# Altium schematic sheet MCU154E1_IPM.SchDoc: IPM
size Letter; Date: Not shown in title block; ApprovedBy: Not shown in title block; CheckedBy: Not shown in title block; Author: Not shown in title block; CompanyName: Not shown in title block; DrawnBy: Hely Zhang; Engineer: Not shown in title block; Organization: Not shown in title block; Address1: Not shown in title block; Address2: Not shown in title block; Address3: Not shown in title block; Address4: Not shown in title block; DocumentNumber: 1; Revision: Use project parameter SCH_Rev; SheetNumber: 3; SheetTotal: 5; PageSetup: Record=PageOptions¦CenterHorizontal=True¦CenterVertical=True¦PrintScale=0.97¦XCorrection=1.00¦YCorrection=1.00¦PrintKind=0¦BorderSize=5000000¦LeftOffset=0¦BottomOffset=0¦Orientation=2¦PaperLength=1000¦PaperWidth=1000¦Scale=100¦PaperSource=15¦PrintQuality=600¦MediaType=1¦DitherType=10¦PaperKind=Letter¦PrintScaleMode=1
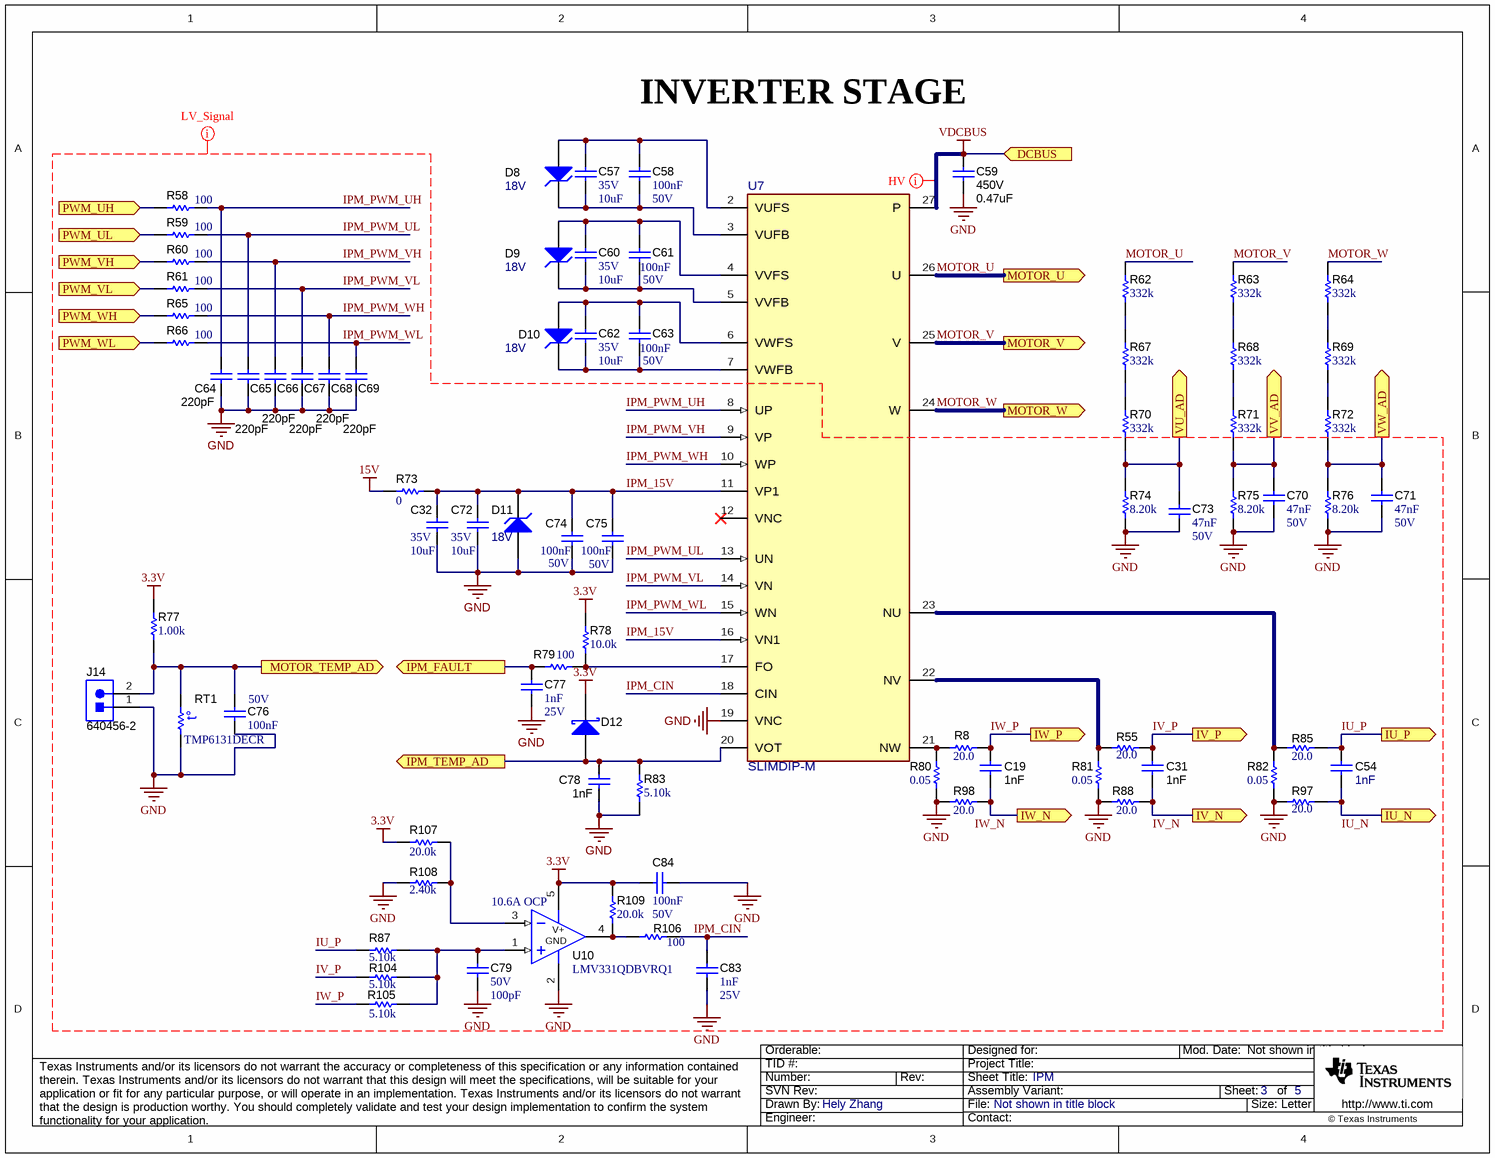
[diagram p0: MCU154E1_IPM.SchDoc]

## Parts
C19  Cap_F: 1nF  [0603]  (hidden comment: GRM188R71E102KA01D)
C31  Cap_F: 1nF  [0603]  (hidden comment: GRM188R71E102KA01D)
C32  VDC_V: 35V  ValueDisplayed: 10uF  [0805_HV]  (hidden comment: GRM21BR6YA106KE43L)
C54  Cap_F: 1nF  [0603]  (hidden comment: GRM188R71E102KA01D)
C57  VDC_V: 35V  ValueDisplayed: 10uF  [0805_HV]  (hidden comment: GRM21BR6YA106KE43L)
C58  Cap_F: 100nF  VDC_V: 50V  [0603]  (hidden comment: GCM188R71H104KA57D)
C59  VDC_V: 450V  ValueDisplayed: 0.47uF  [ECWFD_1260x650x1270]  (hidden comment: ECW-FD2W474Q1)
C60  VDC_V: 35V  ValueDisplayed: 10uF  [0805_HV]  (hidden comment: GRM21BR6YA106KE43L)
C61  Cap_F: 100nF  VDC_V: 50V  [0603]  (hidden comment: GCM188R71H104KA57D)
C62  VDC_V: 35V  ValueDisplayed: 10uF  [0805_HV]  (hidden comment: GRM21BR6YA106KE43L)
C63  Cap_F: 100nF  VDC_V: 50V  [0603]  (hidden comment: GCM188R71H104KA57D)
C64  Cap_F: 220pF  [0603]  (hidden comment: GRM188R71H221KA01D)
C65  Cap_F: 220pF  [0603]  (hidden comment: GRM188R71H221KA01D)
C66  Cap_F: 220pF  [0603]  (hidden comment: GRM188R71H221KA01D)
C67  Cap_F: 220pF  [0603]  (hidden comment: GRM188R71H221KA01D)
C68  Cap_F: 220pF  [0603]  (hidden comment: GRM188R71H221KA01D)
C69  Cap_F: 220pF  [0603]  (hidden comment: GRM188R71H221KA01D)
C70  Cap_F: 47nF  VDC_V: 50V  [0603]  (hidden comment: GRM188R71H473KA61D)
C71  Cap_F: 47nF  VDC_V: 50V  [0603]  (hidden comment: GRM188R71H473KA61D)
C72  VDC_V: 35V  ValueDisplayed: 10uF  [0805_HV]  (hidden comment: GRM21BR6YA106KE43L)
C73  Cap_F: 47nF  VDC_V: 50V  [0603]  (hidden comment: GRM188R71H473KA61D)
C74  Cap_F: 100nF  VDC_V: 50V  [0603]  (hidden comment: GCM188R71H104KA57D)
C75  Cap_F: 100nF  VDC_V: 50V  [0603]  (hidden comment: GCM188R71H104KA57D)
C76  Cap_F: 100nF  VDC_V: 50V  [0603]  (hidden comment: GCM188R71H104KA57D)
C77  Cap_F: 1nF  VDC_V: 25V  [0603]  (hidden comment: GRM188R71E102KA01D)
C78  Cap_F: 1nF  [0603]  (hidden comment: GRM188R71E102KA01D)
C79  VDC_V: 50V  ValueDisplayed: 100pF  [0603]  (hidden comment: GRM1885C1H101JA01D)
C83  Cap_F: 1nF  VDC_V: 25V  [0603]  (hidden comment: GRM188R71E102KA01D)
C84  Cap_F: 100nF  VDC_V: 50V  [0603]  (hidden comment: GCM188R71H104KA57D)
D8  value 18V  [SOD-323]  (hidden comment: MMSZ5248BS-7-F)
D9  value 18V  [SOD-323]  (hidden comment: MMSZ5248BS-7-F)
D10  value 18V  [SOD-323]  (hidden comment: MMSZ5248BS-7-F)
D11  value 18V  [SOD-323]  (hidden comment: MMSZ5248BS-7-F)
D12  BAT54T1G  [SOD-123]  (value not drawn)
J14  640456-2  [TE_640456-2]
R8  ValueDisplayed: 20.0  [0603]  (hidden comment: RC0603FR-0720RL)
R55  ValueDisplayed: 20.0  [0603]  (hidden comment: RC0603FR-0720RL)
R58  ValueDisplayed: 100  [0603]  (hidden comment: RC0603FR-07100RL)
R59  ValueDisplayed: 100  [0603]  (hidden comment: RC0603FR-07100RL)
R60  ValueDisplayed: 100  [0603]  (hidden comment: RC0603FR-07100RL)
R61  ValueDisplayed: 100  [0603]  (hidden comment: RC0603FR-07100RL)
R62  ValueDisplayed: 332k  [1206]  (hidden comment: RC1206FR-07332KL)
R63  ValueDisplayed: 332k  [1206]  (hidden comment: RC1206FR-07332KL)
R64  ValueDisplayed: 332k  [1206]  (hidden comment: RC1206FR-07332KL)
R65  ValueDisplayed: 100  [0603]  (hidden comment: RC0603FR-07100RL)
R66  ValueDisplayed: 100  [0603]  (hidden comment: RC0603FR-07100RL)
R67  ValueDisplayed: 332k  [1206]  (hidden comment: RC1206FR-07332KL)
R68  ValueDisplayed: 332k  [1206]  (hidden comment: RC1206FR-07332KL)
R69  ValueDisplayed: 332k  [1206]  (hidden comment: RC1206FR-07332KL)
R70  ValueDisplayed: 332k  [1206]  (hidden comment: RC1206FR-07332KL)
R71  ValueDisplayed: 332k  [1206]  (hidden comment: RC1206FR-07332KL)
R72  ValueDisplayed: 332k  [1206]  (hidden comment: RC1206FR-07332KL)
R73  ValueDisplayed: 0  [0603]  (hidden comment: RC0603JR-070RL)
R74  ValueDisplayed: 8.20k  [0603]  (hidden comment: RC0603FR-078K2L)
R75  ValueDisplayed: 8.20k  [0603]  (hidden comment: RC0603FR-078K2L)
R76  ValueDisplayed: 8.20k  [0603]  (hidden comment: RC0603FR-078K2L)
R77  ValueDisplayed: 1.00k  [0603]  (hidden comment: RC0603FR-071KL)
R78  ValueDisplayed: 10.0k  [0603]  (hidden comment: RC0603FR-0710KL)
R79  ValueDisplayed: 100  [0603]  (hidden comment: RC0603FR-07100RL)
R80  ValueDisplayed: 0.05  [CSRN2512]  (hidden comment: CSRN2512FT50L0)
R81  ValueDisplayed: 0.05  [CSRN2512]  (hidden comment: CSRN2512FT50L0)
R82  ValueDisplayed: 0.05  [CSRN2512]  (hidden comment: CSRN2512FT50L0)
R83  ValueDisplayed: 5.10k  [0603]  (hidden comment: RC0603FR-075K1L)
R85  ValueDisplayed: 20.0  [0603]  (hidden comment: RC0603FR-0720RL)
R87  ValueDisplayed: 5.10k  [0603]  (hidden comment: RC0603FR-075K1L)
R88  ValueDisplayed: 20.0  [0603]  (hidden comment: RC0603FR-0720RL)
R97  ValueDisplayed: 20.0  [0603]  (hidden comment: RC0603FR-0720RL)
R98  ValueDisplayed: 20.0  [0603]  (hidden comment: RC0603FR-0720RL)
R104  ValueDisplayed: 5.10k  [0603]  (hidden comment: RC0603FR-075K1L)
R105  ValueDisplayed: 5.10k  [0603]  (hidden comment: RC0603FR-075K1L)
R106  ValueDisplayed: 100  [0603]  (hidden comment: RC0603FR-07100RL)
R107  ValueDisplayed: 20.0k  [0603]  (hidden comment: RC0603FR-0720KL)
R108  ValueDisplayed: 2.40k  [0402]  (hidden comment: ERJ-2RKF2401X)
R109  ValueDisplayed: 20.0k  [0603]  (hidden comment: RC0603FR-0720KL)
RT1  TMP6131DECR  [DEC0002A]
U7  SLIMDIP-M  [FP-SLIMDIP-S_SLIMDIP-MFG]
U10  LMV331QDBVRQ1  [DBV0005A_L]

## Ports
DCBUS (in), IPM_FAULT (out), IPM_TEMP_AD (out), IU_N (out), IU_P (out), IV_N (out), IV_P (out), IW_N (out), IW_P (out), MOTOR_TEMP_AD (out), MOTOR_U (out), MOTOR_V (out), MOTOR_W (out), PWM_UH (in), PWM_UL (in), PWM_VH (in), PWM_VL (in), PWM_WH (in), PWM_WL (in), VU_AD (out), VV_AD (out), VW_AD (out)

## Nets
3.3V: C84.1 D12.1(K) R77.2 R78.1 R107.2 R109.1 U10.5(Vcc)
15V: R73.1
GND: C32.2 C59.2 C64.1 C65.1 C66.1 C67.1 C68.1 C69.1 C70.2 C71.2 C72.2 C73.2 C74.2 C75.2 C76.2 C77.2 C78.1 C79.2 C83.2 C84.2 D11.2(A) J14.1 R74.1 R75.1 R76.1 R80.1 R81.1 R82.1 R83.1 R88.1 R97.1 R98.1 R108.1 RT1.1 U7.19(VNC) U10.2(GND)
VDCBUS: C59.1 U7.27(P) ; port DCBUS
IPM_15V: C32.1 C72.1 C74.1 C75.1 D11.1(K) R73.2 U7.11(VP1) U7.16(VN1)
IPM_CIN: C83.1 R106.2 U7.18(CIN)
IPM_FAULT: C77.1 R79.1 ; port IPM_FAULT
IPM_PWM_UH: C64.2 R58.2 U7.8(UP)
IPM_PWM_UL: C65.2 R59.2 U7.13(UN)
IPM_PWM_VH: C66.2 R60.2 U7.9(VP)
IPM_PWM_VL: C67.2 R61.2 U7.14(VN)
IPM_PWM_WH: C68.2 R65.2 U7.10(WP)
IPM_PWM_WL: C69.2 R66.2 U7.15(WN)
IPM_TEMP_AD: C78.2 D12.2(A) R83.2 U7.20(VOT) ; port IPM_TEMP_AD
IU_N: C54.1 R97.2 ; port IU_N
IU_P: C54.2 R85.2 R87.1 ; port IU_P
IV_N: C31.1 R88.2 ; port IV_N
IV_P: C31.2 R55.2 R104.1 ; port IV_P
IW_N: C19.1 R98.2 ; port IW_N
IW_P: C19.2 R8.2 R105.1 ; port IW_P
MOTOR_TEMP_AD: C76.1 J14.2 R77.1 RT1.2 ; port MOTOR_TEMP_AD
MOTOR_U: R62.2 U7.26(U) ; port MOTOR_U
MOTOR_V: R63.2 U7.25(V) ; port MOTOR_V
MOTOR_W: R64.2 U7.24(W) ; port MOTOR_W
PWM_UH: R58.1 ; port PWM_UH
PWM_UL: R59.1 ; port PWM_UL
PWM_VH: R60.1 ; port PWM_VH
PWM_VL: R61.1 ; port PWM_VL
PWM_WH: R65.1 ; port PWM_WH
PWM_WL: R66.1 ; port PWM_WL
VU_AD: C73.1 R70.1 R74.2 ; port VU_AD
VV_AD: C70.1 R71.1 R75.2 ; port VV_AD
VW_AD: C71.1 R72.1 R76.2 ; port VW_AD
NetC57_1: C57.1 C58.1 D8.2(A) U7.2(VUFS)
NetC57_2: C57.2 C58.2 D8.1(K) U7.3(VUFB)
NetC60_1: C60.1 C61.1 D9.2(A) U7.4(VVFS)
NetC60_2: C60.2 C61.2 D9.1(K) U7.5(VVFB)
NetC62_1: C62.1 C63.1 D10.2(A) U7.6(VWFS)
NetC62_2: C62.2 C63.2 D10.1(K) U7.7(VWFB)
NetC79_1: C79.1 R87.2 R104.2 R105.2 U10.1(IN+)
NetR8_1: R8.1 R80.2 U7.21(NW)
NetR55_1: R55.1 R81.2 U7.22(NV)
NetR62_1: R62.1 R67.2
NetR63_1: R63.1 R68.2
NetR64_1: R64.1 R69.2
NetR67_1: R67.1 R70.2
NetR68_1: R68.1 R71.2
NetR69_1: R69.1 R72.2
NetR78_2: R78.2 R79.2 U7.17(FO)
NetR82_2: R82.2 R85.1 U7.23(NU)
NetR106_1: R106.1 R109.2 U10.4(OUT)
NetR107_1: R107.1 R108.2 U10.3(IN-)

Not connected (* = marked no-connect by the designer): U7 12(VNC)*

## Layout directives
net class HV: VDCBUS
net class LV_Signal: 3.3V, 15V, GND, IPM_15V, IPM_CIN, IPM_PWM_UH, IPM_PWM_UL, IPM_PWM_VH, IPM_PWM_VL, IPM_PWM_WH, IPM_PWM_WL, IU_N, IU_P, IV_N, IV_P, IW_N, IW_P, MOTOR_U, MOTOR_V, MOTOR_W, VDCBUS

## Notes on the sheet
- INVERTER STAGE
- (near U10) 10.6A OCP

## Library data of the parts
C19 C31 C54 C78 = CMP-0007402-3: CAP, CERM, 1000 pF, 25 V, +/- 10%, X7R, 0603; Manufacturer: MuRata; TaMin_C: -55°C; Polarized: N; SizeAreaWB_mm2: 4.68; Value1: Unknown; U/M: EA; Value: 1000pF; TaMax_C: 125°C; SizeZ_mm: 1; SizeX_mm: 1.6; SizeY_mm: 0.8; Value2: 25V; SizeArea_mm2: 1.28; AEC Category: Q200
C32 C57 C60 C62 C72 = CMP-0008310-1: CAP, CERM, 10 uF, 35 V, +/- 10%, X5R, 0805; Manufacturer: MuRata; TaMin_C: -55°C; Polarized: N; SizeAreaWB_mm2: 6.75; Value1: Unknown; U/M: EA; Value: 10uF; TaMax_C: 85°C; SizeZ_mm: 1.45; SizeX_mm: 2; SizeY_mm: 1.25; Cap_Case: 0805; SizeArea_mm2: 2.5; Cap_F: 10µF; AEC Category: Q200
C58 C61 C63 C74-C76 C84 = CMP-0007144-4: CAP, CERM, 0.1 uF, 50 V, +/- 10%, X7R, 0603; Manufacturer: MuRata; TaMin_C: -55°C; ESR_ohm: 20m; Polarized: N; SizeAreaWB_mm2: 4.68; Value1: 0.02 ohm; U/M: EA; Value: 0.1uF; TaMax_C: 125°C; SizeZ_mm: 1; SizeX_mm: 1.6; SizeY_mm: 0.8; SizeArea_mm2: 1.28; IRMS_A: 1.84A; AEC Category: Q200
C59 = CMP-0012508-3: CAP, Film, 0.47 uF, 450 V, +/- 10%, TH; Manufacturer: Panasonic; TaMin_C: -40°C; Polarized: N; Value1: Unknown; Value: 0.47uF; TaMax_C: 110°C; Cap_Case: 12.6x6.5x12.7mm; Cap_F: 470nF; AEC Category: Q200
C64-C69 = CMP-0007442-5: CAP, CERM, 220 pF, 50 V, +/- 10%, X7R, 0603; Manufacturer: MuRata; TaMin_C: -55°C; Polarized: N; SizeAreaWB_mm2: 4.68; Value1: Unknown; U/M: EA; Value: 220pF; TaMax_C: 125°C; SizeZ_mm: 1; SizeX_mm: 1.6; SizeY_mm: 0.8; Value2: 50V; SizeArea_mm2: 1.28; AEC Category: Q200
C70 C71 C73 = CMP-0007457-2: CAP, CERM, 0.047 uF, 50 V, +/- 10%, X7R, 0603; Manufacturer: MuRata; TaMin_C: -55°C; Polarized: N; SizeAreaWB_mm2: 4.68; Value1: Unknown; U/M: EA; TaMax_C: 125°C; SizeZ_mm: 1; SizeX_mm: 1.6; SizeY_mm: 0.8; SizeArea_mm2: 1.28; AEC Category: Q200
C77 C83 = CMP-0007402-1: CAP, CERM, 1000 pF, 25 V, +/- 10%, X7R, 0603; Manufacturer: MuRata; TaMin_C: -55°C; Polarized: N; SizeAreaWB_mm2: 4.68; Value1: Unknown; U/M: EA; Value: 1000pF; TaMax_C: 125°C; SizeZ_mm: 1; SizeX_mm: 1.6; SizeY_mm: 0.8; SizeArea_mm2: 1.28; AEC Category: Q200
C79 = CMP-0007171-4: CAP, CERM, 100 pF, 50 V, +/- 5%, C0G/NP0, 0603; Manufacturer: MuRata; TaMin_C: -55°C; Polarized: N; SizeAreaWB_mm2: 4.68; Value1: Unknown; U/M: EA; Value: 100pF; TaMax_C: 125°C; SizeZ_mm: 1; SizeX_mm: 1.6; SizeY_mm: 0.8; SizeArea_mm2: 1.28; AEC Category: Q200
D8-D11 = CMP-0005835-4: Diode, Zener, 18 V, 200 mW, SOD-323; Manufacturer: Diodes Inc.; Value1: 0.2W; SizeArea_mm2: 3.645; AEC Category: Q101; Power_W: 200mW; SizeAreaWB_mm2: 8.695; SizeY_mm: 1.35; RJA_CperW: 350; SizeZ_mm: 1; SizeX_mm: 2.7
D12 = CMP-0028457-2: Diode, Schottky, 30 V, 0.2 A, SOD-123; Manufacturer: ON Semiconductor; SizeArea_mm2: 6.545; Io_A: 200mA; SizeX_mm: 3.85; Value1: 0.2A; SizeY_mm: 1.7; AEC Category: Q101; Vf_V: 800mV; TJmax_C: 125°C; Green_Lifecycle: Not Set; RJC_CperW: 174; Value: 30V; Value2: 0.8V; SizeAreaWB_mm2: 13.095; Green_REACh: Incomplete; SizeZ_mm: 1.35
J14 = CMP-0054970-1: Header, 2.54mm, 2x1, Tin, TH; Manufacturer: TE Connectivity; CNHeader: TRUE; Current_A: 5A; Shrouded: N; Gender: Male; Cert_CSA: Y; Voltage_V: 250V; Row_Count: 1; Pitch_mm: 2.54; CT: FALSE
R8 R55 R85 R88 R97 R98 = CMP-0022908-4: RES, 20.0, 1%, 0.1 W, 0603; Manufacturer: Yageo; Power_W: 100mW; TempCo: 100 ppm/C; Value_Code: 20R0; Value: 20.0; EIA_Code: E96; Res_ohm: 20; SizeX_mm: 1.6; SizeY_mm: 0.8; SizeZ_mm: 1; Value2: 0.1W; SizeArea_mm2: 1.28; AEC Qualified: N; VDC_V: 75V; AEC Category: Q200; SizeAreaWB_mm2: 4.68
R58-R61 R65 R66 R79 R106 = CMP-0022736-4: RES, 100, 1%, 0.1 W, 0603; Manufacturer: Yageo; Power_W: 100mW; TempCo: 100 ppm/C; Value_Code: 100R; Value: 100; EIA_Code: E96; SizeX_mm: 1.6; SizeY_mm: 0.8; SizeZ_mm: 1; Value2: 0.1W; SizeArea_mm2: 1.28; AEC Qualified: N; VDC_V: 75V; AEC Category: Q200; SizeAreaWB_mm2: 4.68
R62-R64 R67-R72 = CMP-0018207-2: RES, 332 k, 1%, 0.25 W, 1206; Manufacturer: Yageo America; Power_W: 250mW; TempCo: 100 ppm/C; U/M: EA; Value: 332k; EIA_Code: E96; SizeX_mm: 3.2; SizeY_mm: 1.6; SizeZ_mm: 1.35; Value2: 0.25W; SizeArea_mm2: 5.12; VDC_V: 200V; AEC Category: Q200
R73 = CMP-0025885-5: RES, 0, 5%, 0.1 W, 0603; Manufacturer: Yageo; Power_W: 100mW; TempCo: 200 ppm/C; Value_Code: 0000; Value: 0; EIA_Code: E24; SizeX_mm: 1.6; SizeZ_mm: 1; Value2: 0.1W; SizeArea_mm2: 1.28; AEC Qualified: N; VDC_V: 75V; AEC Category: Q200; SizeY_mm: 0.8; SizeAreaWB_mm2: 4.68
R74-R76 = CMP-0023308-5: RES, 8.20 k, 1%, 0.1 W, 0603; Manufacturer: Yageo; Power_W: 100mW; TempCo: 100 ppm/C; Value_Code: 8k20; Value: 8.20k; Res_ohm: 8.2k; SizeX_mm: 1.6; SizeY_mm: 0.8; SizeZ_mm: 1; Value2: 0.1W; SizeArea_mm2: 1.28; AEC Qualified: N; VDC_V: 75V; AEC Category: Q200; SizeAreaWB_mm2: 4.68
R77 = CMP-0022895-5: RES, 1.00 k, 1%, 0.1 W, 0603; Manufacturer: Yageo; Power_W: 100mW; TempCo: 100 ppm/C; Value_Code: 1k00; Value: 1.00k; EIA_Code: E96; Res_ohm: 1k; SizeX_mm: 1.6; SizeY_mm: 0.8; SizeZ_mm: 1; Value2: 0.1W; SizeArea_mm2: 1.28; AEC Qualified: N; VDC_V: 75V; AEC Category: Q200; SizeAreaWB_mm2: 4.68
R78 = CMP-0022746-5: RES, 10.0 k, 1%, 0.1 W, 0603; Manufacturer: Yageo; Power_W: 100mW; TempCo: 100 ppm/C; Value_Code: 10k0; Value: 10.0k; EIA_Code: E96; Res_ohm: 10k; SizeX_mm: 1.6; SizeY_mm: 0.8; SizeZ_mm: 1; Value2: 0.1W; SizeArea_mm2: 1.28; AEC Qualified: N; VDC_V: 75V; AEC Category: Q200; SizeAreaWB_mm2: 4.68
R80-R82 = CMP-0015791-2: RES, 0.05, 1%, 2 W, 2512; Manufacturer: Stackpole Electronics Inc; Power_W: 2W; TempCo: 200 ppm/C; Value_Code: R050; U/M: EA; Value: 0.05; EIA_Code: E96; Res_ohm: 50m; SizeX_mm: 6.35; SizeY_mm: 3.15; SizeZ_mm: 0.7; SizeArea_mm2: 20.0025; AEC Qualified: N; AEC Category: Q200
R83 R87 R104 R105 = CMP-0023198-5: RES, 5.10 k, 1%, 0.1 W, 0603; Manufacturer: Yageo; Power_W: 100mW; TempCo: 100 ppm/C; Value_Code: 5k10; Value: 5.10k; Res_ohm: 5.1k; SizeX_mm: 1.6; SizeY_mm: 0.8; SizeZ_mm: 1; Value2: 0.1W; SizeArea_mm2: 1.28; AEC Qualified: N; VDC_V: 75V; AEC Category: Q200; SizeAreaWB_mm2: 4.68
R107 R109 = CMP-0022906-5: RES, 20.0 k, 1%, 0.1 W, 0603; Manufacturer: Yageo; Power_W: 100mW; TempCo: 100 ppm/C; Value_Code: 20k0; Value: 20.0k; EIA_Code: E96; Res_ohm: 20k; SizeX_mm: 1.6; SizeY_mm: 0.8; SizeZ_mm: 1; Value2: 0.1W; SizeArea_mm2: 1.28; AEC Qualified: N; VDC_V: 75V; AEC Category: Q200; SizeAreaWB_mm2: 4.68
R108 = CMP-0026685-1: RES, 2.40 k, 1%, 0.1 W, AEC-Q200 Grade 0, 0402; Manufacturer: Panasonic; Power_W: 100mW; TempCo: 100 ppm/C; Value_Code: 2k40; U/M: EA; Value: 2.40k; Res_ohm: 2.4k; SizeX_mm: 1; SizeY_mm: 0.5; SizeZ_mm: 0.6; Value2: 0.1W; AEC Qualified: Y; AEC Grade: 0; AEC Category: Q200
RT1 = CMP-0084566-1: Thermistor, DEC0002A (X1SON-2); Alternate Manufacturer: Texas Instruments; Alternate PartNumber: TMP6131DECT; CompType: IC; AEC Category: Q200; SizeX_mm: 1; AEC Qualified: N; SizeZ_mm: 0.5; SizeArea_mm2: 0.6; SizeAreaWB_mm2: 3.2
U7 = CMP-0033830-3: RC-IGBT inverter bridge for three phase DC-to-AC power conversion; Manufacturer: Mitsubishi Electric; SizeZ_mm: 6mm; AEC Qualified: No; Standoff Height: 1.4mm; TJmax_C: +150°C
U10 = CMP-0075716-1: GENERAL-PURPOSE LOW-VOLTAGE COMPARATOR, DBV0005A (SOT-23-5); Manufacturer: Texas Instruments; SizeAreaWB_mm2: 14.82; SizeArea_mm2: 8.12; SizeZ_mm: 1.45; SizeY_mm: 2.9; U/M: EA; CompType: IC; SizeX_mm: 2.8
